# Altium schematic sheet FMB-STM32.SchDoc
size A3
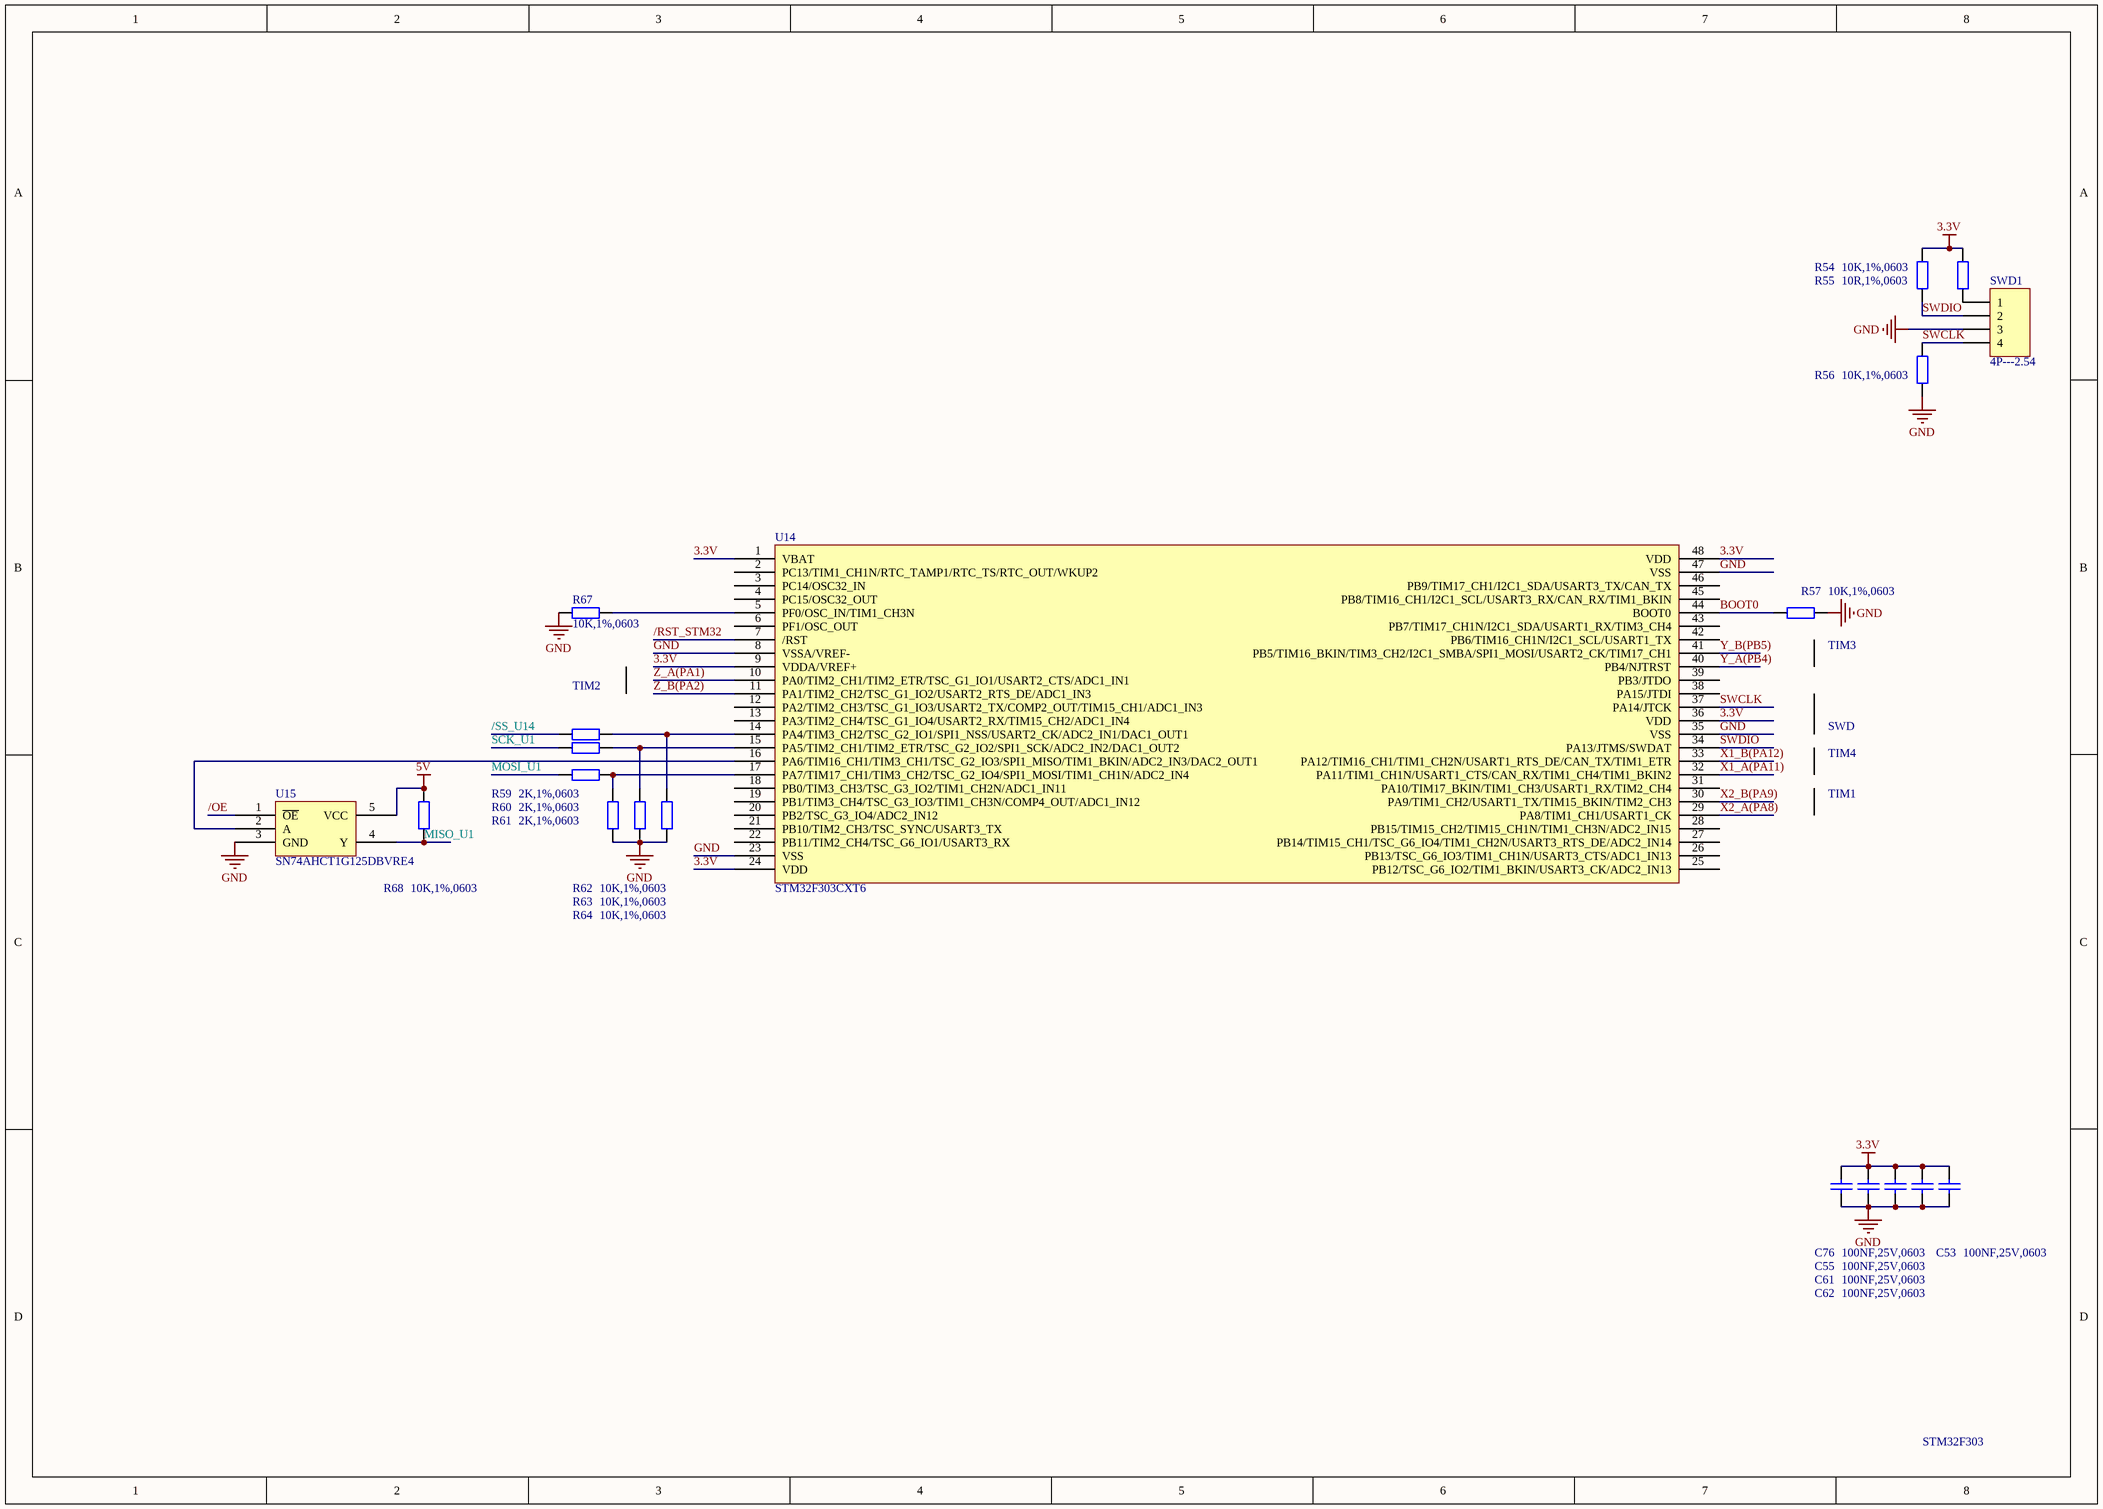
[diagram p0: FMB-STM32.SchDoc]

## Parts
C53  100NF,25V,0603  [RC0603]
C55  100NF,25V,0603  [RC0603]
C61  100NF,25V,0603  [RC0603]
C62  100NF,25V,0603  [RC0603]
C76  100NF,25V,0603  [RC0603]
R54  10K,1%,0603  [RC0603]
R55  10R,1%,0603  [RC0603]
R56  10K,1%,0603  [RC0603]
R57  10K,1%,0603  [RC0603]
R59  2K,1%,0603  [RC0603]
R60  2K,1%,0603  [RC0603]
R61  2K,1%,0603  [RC0603]
R62  10K,1%,0603  [RC0603]
R63  10K,1%,0603  [RC0603]
R64  10K,1%,0603  [RC0603]
R67  10K,1%,0603  [RC0603]
R68  10K,1%,0603  [RC0603]
SWD1  4P---2.54  [HDR1X4]
U14  STM32F303CXT6  [LQFP-48]
U15  SN74AHCT1G125DBVRE4  [SOT-23-5]

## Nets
3.3V: C53.1 C55.1 C61.1 C62.1 C76.1 R54.1 R55.1 U14.1(VBAT) U14.9(VDDA/VREF+) U14.24(VDD) U14.36(VDD) U14.48(VDD)
5V: R68.2 U15.5(VCC)
GND: C53.2 C55.2 C61.2 C62.2 C76.2 R56.1 R57.1 R62.1 R63.1 R64.1 R67.2 SWD1.3 U14.8(VSSA/VREF-) U14.23(VSS) U14.35(VSS) U14.47(VSS) U15.3(GND)
/OE: U15.1(~{OE})
/RST_STM32: U14.7(/RST)
/SS_U14: R59.1
BOOT0: R57.2 U14.44(BOOT0)
MISO_U1: R68.1 U15.4(Y)
MOSI_U1: R61.1
SCK_U1: R60.1
SWCLK: R56.2 SWD1.4 U14.37(PA14/JTCK)
SWDIO: R54.2 SWD1.2 U14.34(PA13/JTMS/SWDAT)
X1_A(PA11): U14.32(PA11/TIM1_CH1N/USART1_CTS/CAN_RX/TIM1_CH4/TIM1_BKIN2)
X1_B(PA12): U14.33(PA12/TIM16_CH1/TIM1_CH2N/USART1_RTS_DE/CAN_TX/TIM1_ETR)
X2_A(PA8): U14.29(PA8/TIM1_CH1/USART1_CK)
X2_B(PA9): U14.30(PA9/TIM1_CH2/USART1_TX/TIM15_BKIN/TIM2_CH3)
Y_A(PB4): U14.40(PB4/NJTRST)
Y_B(PB5): U14.41(PB5/TIM16_BKIN/TIM3_CH2/I2C1_SMBA/SPI1_MOSI/USART2_CK/TIM17_CH1)
Z_A(PA1): U14.10(PA0/TIM2_CH1/TIM2_ETR/TSC_G1_IO1/USART2_CTS/ADC1_IN1)
Z_B(PA2): U14.11(PA1/TIM2_CH2/TSC_G1_IO2/USART2_RTS_DE/ADC1_IN3)
NetR55_2: R55.2 SWD1.1
NetR59_2: R59.2 R64.2 U14.14(PA4/TIM3_CH2/TSC_G2_IO1/SPI1_NSS/USART2_CK/ADC2_IN1/DAC1_OUT1)
NetR60_2: R60.2 R63.2 U14.15(PA5/TIM2_CH1/TIM2_ETR/TSC_G2_IO2/SPI1_SCK/ADC2_IN2/DAC1_OUT2)
NetR61_2: R61.2 R62.2 U14.17(PA7/TIM17_CH1/TIM3_CH2/TSC_G2_IO4/SPI1_MOSI/TIM1_CH1N/ADC2_IN4)
NetR67_1: R67.1 U14.5(PF0/OSC_IN/TIM1_CH3N)
NetU14_16: U14.16(PA6/TIM16_CH1/TIM3_CH1/TSC_G2_IO3/SPI1_MISO/TIM1_BKIN/ADC2_IN3/DAC2_OUT1) U15.2(A)

Not connected (* = marked no-connect by the designer): U14 2(PC13/TIM1_CH1N/RTC_TAMP1/RTC_TS/RTC_OUT/WKUP2) 3(PC14/OSC32_IN) 4(PC15/OSC32_OUT) 6(PF1/OSC_OUT) 12(PA2/TIM2_CH3/TSC_G1_IO3/USART2_TX/COMP2_OUT/TIM15_CH1/ADC1_IN3) 13(PA3/TIM2_CH4/TSC_G1_IO4/USART2_RX/TIM15_CH2/ADC1_IN4) 18(PB0/TIM3_CH3/TSC_G3_IO2/TIM1_CH2N/ADC1_IN11) 19(PB1/TIM3_CH4/TSC_G3_IO3/TIM1_CH3N/COMP4_OUT/ADC1_IN12) 20(PB2/TSC_G3_IO4/ADC2_IN12) 21(PB10/TIM2_CH3/TSC_SYNC/USART3_TX) 22(PB11/TIM2_CH4/TSC_G6_IO1/USART3_RX) 25(PB12/TSC_G6_IO2/TIM1_BKIN/USART3_CK/ADC2_IN13) 26(PB13/TSC_G6_IO3/TIM1_CH1N/USART3_CTS/ADC1_IN13) 27(PB14/TIM15_CH1/TSC_G6_IO4/TIM1_CH2N/USART3_RTS_DE/ADC2_IN14) 28(PB15/TIM15_CH2/TIM15_CH1N/TIM1_CH3N/ADC2_IN15) 31(PA10/TIM17_BKIN/TIM1_CH3/USART1_RX/TIM2_CH4) 38(PA15/JTDI) 39(PB3/JTDO) 42(PB6/TIM16_CH1N/I2C1_SCL/USART1_TX) 43(PB7/TIM17_CH1N/I2C1_SDA/USART1_RX/TIM3_CH4) 45(PB8/TIM16_CH1/I2C1_SCL/USART3_RX/CAN_RX/TIM1_BKIN) 46(PB9/TIM17_CH1/I2C1_SDA/USART3_TX/CAN_TX)

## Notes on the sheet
- (near R57) TIM3
- TIM2
- SWD
- TIM4
- TIM1
- STM32F303

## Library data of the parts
C53 C55 C61 C62 C76 = Cap: Capacitor; Value: 100pF
R54-R57 R59-R64 R67 R68 = Res2: Resistor; Value: 1K
SWD1 = Header 4: Header, 4-Pin
U14 = STM32F303
U15 = 74AHCT1G125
